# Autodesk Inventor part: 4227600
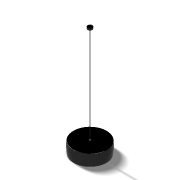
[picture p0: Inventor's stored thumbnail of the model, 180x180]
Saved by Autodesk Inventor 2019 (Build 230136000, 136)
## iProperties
Created: 2020-11
Part Number: 4227600
Material: Generic
Document SubType Name: Modeling
Designer: user
Mass: 1726.94 g
Surface Area: 6661.78 cm^2
Volume: 1015.85 cm^3
Density: 1 g/cm^3
Appearance: Snow
Author: user
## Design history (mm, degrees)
node "Sketch1"
sketch "Sketch2"
  geometry: L1 (-1.5, 119.991)-(-171.5, 119.991); L2 (-1.5, 116.99)-(-167.49, 116.99); L3 (-159.49, 2.99)-(-167.49, 2.99); L4 (-159.49, 0.235)-(-168.538, 0.235); L5 (-171.5, 119.991)-(-168.5, 119.991); L6 (-175, 59.99)-(-175, 185.727); L7 (-167.49, 2.99)-(-159.49, 2.99); L8 (-159.49, 2.99)-(-159.49, 0.235); L9 (0, 129.991)-(0, 1119.99); L10 (0, 1119.99)-(3, 1119.99); L11 (3, 1119.99)-(3, 119.977); L12 (0, 1119.99)-(-1.5, 1119.99); L13 (-1.5, 1119.99)-(-1.5, 1129.99); L14 (-1.5, 1129.99)-(-22, 1129.99); L15 (-22, 1129.99)-(-22, 1149.99); L16 (-22, 1149.99)-(3, 1149.99); L17 (3, 1119.99)-(3, 1149.99); L18 (3, 119.977)-(3, -0.01); L19 (-1.5, 119.991)-(-1.5, 129.991); L20 (-1.5, 129.991)-(0, 129.991); L21 (-1.5, 116.99)-(3, 116.99); A1 r 362.5 centre (187.389, 68.953) between (-171.5, 119.991) and (-168.538, 0.235); A2 r 362.5 centre (190.5, 59.99) between (-167.49, 116.99) and (-167.49, 2.99); 1 further point
  constraints: 42 end point, 6 perpendicular, 5 horizontal, 5 point on circle, 4 point on line, 4 vertical, 3 parallel, 2 centre point
  dimensions: "d1" = 120 distance of point (0, 0) L1.start; "d2" = 170 distance of L1.start L1.end; "d3" = 117 distance of point (0, 0) L2.start; "d12" = 3 distance of L1.end L5.end; "d14" = 8 distance of L3.start L3.end; "d15" = 1000 distance of L1.start L9.end; "d18" = 10 distance of L12.end L13.end; "d20" = 20 distance of L14.end L15.end; "d21" = 175 distance between parallel lines of L9 L6; "d22" = 3 distance between parallel lines of L11 L9; "d23" = 25 distance between parallel lines of L17 L15; "d26" = 10 distance of L1.start L19.end
revolve "Revolution1" sketch "Sketch2" stored, may be unused: angle "d24" = 90 deg
workplane "Work Plane1"
sketch "Sketch3"
  geometry: C1 r 164.994 at (0, 0); 1 further point
  constraints: 1 centre point, 1 coincident
extrude "Extrusion1" join sketch "Sketch3" distance "d28" = 3; taper "d29" = 0 deg
fillet "Fillet1" dims "d30" = 2
fillet "Fillet2" dims "d31" = 4
body "Solid1"
other parameters: "sa_0" = 4, "d27" = 3
